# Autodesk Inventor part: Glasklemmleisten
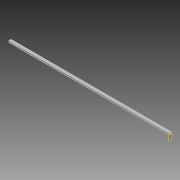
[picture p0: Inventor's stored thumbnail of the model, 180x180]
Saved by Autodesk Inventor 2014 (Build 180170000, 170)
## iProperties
Created: 2013-09
Part Number: Glasklemmleisten
Material: Aluminium 6061
Document SubType Name: Modeling
Designer: Stefan Tammegger
Mass: 1852.54 g
Surface Area: 9037.84 cm^2
Volume: 683.593 cm^3
Density: 2.71 g/cm^3
Appearance: Aluminium - flach
Author: Stefan Tammegger
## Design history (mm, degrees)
node "Blöcke"
  sketch "Glasklemmleiste oben"
    geometry: L1 (-37.726, 59.874)-(-30.726, 59.874); L2 (-30.726, 119.874)-(-37.726, 119.874); L3 (-39.726, 117.874)-(-39.726, 61.874); L4 (-30.726, 59.874)-(-30.726, 74.874); L5 (-30.726, 119.874)-(-30.726, 104.874); L6 (-38.226, 74.874)-(-38.226, 104.874); L7 (-30.726, 74.874)-(-38.226, 74.874); L8 (-30.726, 104.874)-(-38.226, 104.874); L9 (-30.726, 119.874)-(-24.726, 119.874); L10 (-24.726, 119.874)-(-24.726, 104.874); L11 (-24.726, 104.874)-(-30.726, 104.874); L12 (-30.726, 59.874)-(-24.726, 59.874); L13 (-24.726, 59.874)-(-24.726, 74.874); L14 (-24.726, 74.874)-(-30.726, 74.874); L15 (-38.226, 61.374)-(-26.226, 61.374); L16 (-26.226, 61.374)-(-26.226, 73.374); L17 (-26.226, 73.374)-(-38.226, 73.374); L18 (-38.226, 73.374)-(-38.226, 61.374); L19 (-38.226, 106.374)-(-26.226, 106.374); L20 (-26.226, 106.374)-(-26.226, 118.374); L21 (-26.226, 118.374)-(-38.226, 118.374); L22 (-38.226, 118.374)-(-38.226, 106.374); A1 r 2 centre (-37.726, 61.874) between (-39.726, 61.874) and (-37.726, 59.874); A2 r 2 centre (-37.726, 117.874) between (-37.726, 119.874) and (-39.726, 117.874); 2 further points
    constraints: 44 end point, 10 parallel, 5 perpendicular, 4 point on circle, 4 tangent, 3 horizontal, 2 centre point, 2 point on line, 1 collinear, 1 equal radius, 1 midpoint
    dimensions: "d0" = 9 distance of point (-39.726, 119.874) L2.start; "d1" = 60 distance of L2.start L1.end; "d2" = 15 distance of L1.end L4.end; "d3" = 15 distance of L2.start L5.end; "d4" = 1.5 distance between parallel lines of L3 L6; "d5" = 6 distance of L2.start L9.end; "d6" = 6 distance of L1.end L12.end; "d10" = 1.5 distance between parallel lines of L13 L16; "d11" = 1.5 distance between parallel lines of L1 L15; "d12" = 1.5 distance between parallel lines of L3 L18; "d13" = 1.5 distance between parallel lines of L7 L17; "d14" = 1.5 distance between parallel lines of L8 L19; "d15" = 1.5 distance between parallel lines of L10 L20; "d16" = 1.5 distance between parallel lines of L2 L21; "d17" = 1.5 distance between parallel lines of L3 L22; "d18" = 2 radius of A1
  sketch "Glasklemmleiste unten"
    geometry: L1 (-60.068, 49.16)-(-60.068, 109.16); L2 (-60.068, 109.16)-(-63.068, 109.16); L3 (-60.068, 49.16)-(-63.068, 49.16); L4 (-63.068, 74.16)-(-67.068, 74.16); L5 (-67.068, 74.16)-(-67.068, 75.66); L6 (-67.068, 75.66)-(-63.068, 75.66); L7 (-63.068, 49.16)-(-63.068, 74.16); L8 (-60.068, 79.16)-(-63.068, 79.16); L9 (-63.068, 84.16)-(-67.068, 84.16); L10 (-67.068, 84.16)-(-67.068, 82.66); L11 (-67.068, 82.66)-(-63.068, 82.66); L12 (-63.068, 75.66)-(-63.068, 82.66); L13 (-63.068, 84.16)-(-63.068, 109.16); 1 further point
    constraints: 26 end point, 5 perpendicular, 4 symmetric about line, 1 coincident, 1 midpoint, 1 parallel
    dimensions: "d21" = 60 distance of L1.start L1.end; "d22" = 3 distance of L1.end L2.end; "d23" = 3 distance of L1.start L3.end; "d24" = 4 distance of L4.start L4.end; "d25" = 1.5 distance of L4.end L5.end; "d26" = 25 distance between parallel lines of L3 L4
workplane "Arbeitsebene1"
sketch "Skizze1"
  geometry: L1 (46, 30)-(-46, 30) reference; L2 (-50, 26)-(-50, -26) reference
  constraints: 1 horizontal
  dimensions: "d7" = 17 dimension on L2
  node "Glasklemmleiste oben:1" dims "d7" = 17
  node "Referenz1"
  node "Referenz2"
workplane "Arbeitsebene2"
workplane "Arbeitsebene3"
extrude "Extrusion2" new body sketch "Skizze1" stored distance "d19" = 10; taper "d20" = 0 deg
sketch "Skizze2"
  geometry: L1 (-50, 26)-(-50, -26) reference
  constraints: 2 vertical
extrude "Extrusion3" new body sketch "Skizze2" stored distance "d27" = 10; taper "d28" = 0 deg
sketch "Skizze3" dims "d37" = 10
  geometry: L1 (0, 56)-(0, 0) reference; L2 (3330, 56)-(3330, 0) reference; L3 (3330, 56)-(0, 56) reference; 9 further points
  constraints: 1 horizontal, 7 other
  dimensions: "d30" = 60 distance from line of point (60, 28) L1; "d31" = 28 distance from line of point (60, 28) L3; "d34" = 460 distance of point (60, 28) point (520, 28); "d39" = 50 distance from line of L2 point (3280, 28) (derived)
hole "Bohrung1" sketch "Skizze3" at (60, 28), (520, 28), (980, 28), (1440, 28), (1900, 28), (2360, 28), (2820, 28), (3280, 28) diameter "d40" = 6; stored, may be unused: countersink angle "d44" = 90 deg, drill point angle "d46" = 118 deg; dims "d41" = 6, "d42" = 4, "d43" = 2, "d45" = 8
node "Volumenkörper2"
node "Referenz3"
node "Volumenkörper3"
node "Glasklemmleiste unten:1"
